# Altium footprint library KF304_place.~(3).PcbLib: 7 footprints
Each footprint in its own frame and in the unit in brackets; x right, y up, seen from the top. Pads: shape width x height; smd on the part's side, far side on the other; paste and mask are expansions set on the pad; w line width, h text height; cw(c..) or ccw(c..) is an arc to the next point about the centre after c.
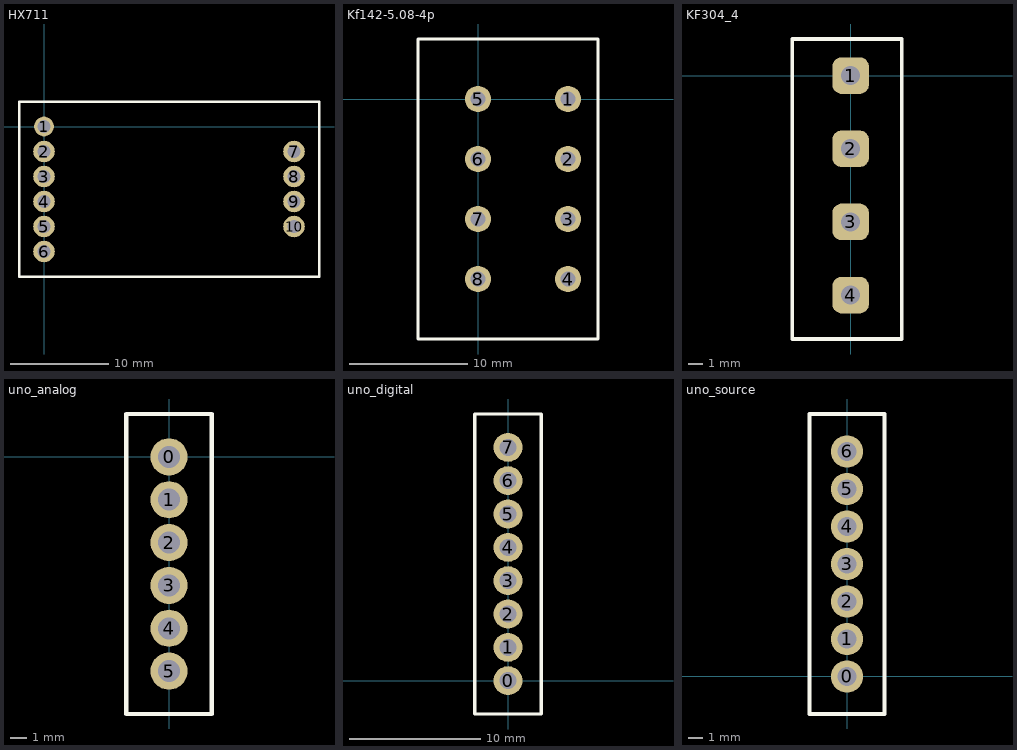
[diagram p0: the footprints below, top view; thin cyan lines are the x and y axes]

## HX711 [mm]
height 5
pads (10):
  round 2 hole 1.3 paste+0 mask+0.102: 1(0,0)
  round 2.2 hole 1.3 paste+0 mask+0.102: 2(0,-2.54) 3(0,-5.08) 4(0,-7.62) 5(0,-10.16) 6(0,-12.7) 7(25.4,-2.54) 8(25.4,-5.08) 9(25.4,-7.62) 10(25.4,-10.16)
Top Overlay:
  lines w0.254: -2.54,-15.24 -2.54,2.54 27.94,2.54 27.94,-15.24 -2.54,-15.24

## Kf142-5.08-4p [mm]
height 15
pads (8):
  round 2.2 hole 1.3 paste+0 mask+0.102: 1(7.62,0) 2(7.62,-5.08) 3(7.62,-10.16) 4(7.62,-15.24) 5(0,0) 6(0,-5.08) 7(0,-10.16) 8(0,-15.24)
Top Overlay:
  lines w0.254: -5.08,-20.32 10.16,-20.32 10.16,5.08 -5.08,5.08 -5.08,-20.32

## KF304_4 [mm]
height 14.5
pads (4):
  rrect50% 2.5x2.5 hole 1.3 paste+0 mask+0.102: 1(0,0) 2(0,-5) 3(0,-10) 4(0,-15)
Top Overlay:
  lines w0.254: -4,-18 -4,2.5 3.5,2.5 3.5,-18 -4,-18

## PCBComponent_1 [mm]

## uno_analog [mm]
pads (6):
  round 2.2 hole 1.3 paste+0 mask+0.102: 0(0,0) 1(0,-2.54) 2(0,-5.08) 3(0,-7.62) 4(0,-10.16) 5(0,-12.7)
Top Overlay:
  lines w0.254: -2.54,-15.24 2.54,-15.24 2.54,2.54 -2.54,2.54 -2.54,-15.24

## uno_digital [mm]
pads (8):
  round 2.2 hole 1.3 paste+0 mask+0.102: 0(0,0) 1(0,2.54) 2(0,5.08) 3(0,7.62) 4(0,10.16) 5(0,12.7) 6(0,15.24) 7(0,17.78)
Top Overlay:
  lines w0.254: -2.54,-2.54 2.54,-2.54 2.54,20.32 -2.54,20.32 -2.54,-2.54

## uno_source [mm]
pads (7):
  round 2.2 hole 1.3 paste+0 mask+0.102: 0(0,0) 1(0,2.54) 2(0,5.08) 3(0,7.62) 4(0,10.16) 5(0,12.7) 6(0,15.24)
Top Overlay:
  lines w0.254: -2.54,-2.54 -2.54,17.78 2.54,17.78 2.54,-2.54 -2.54,-2.54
